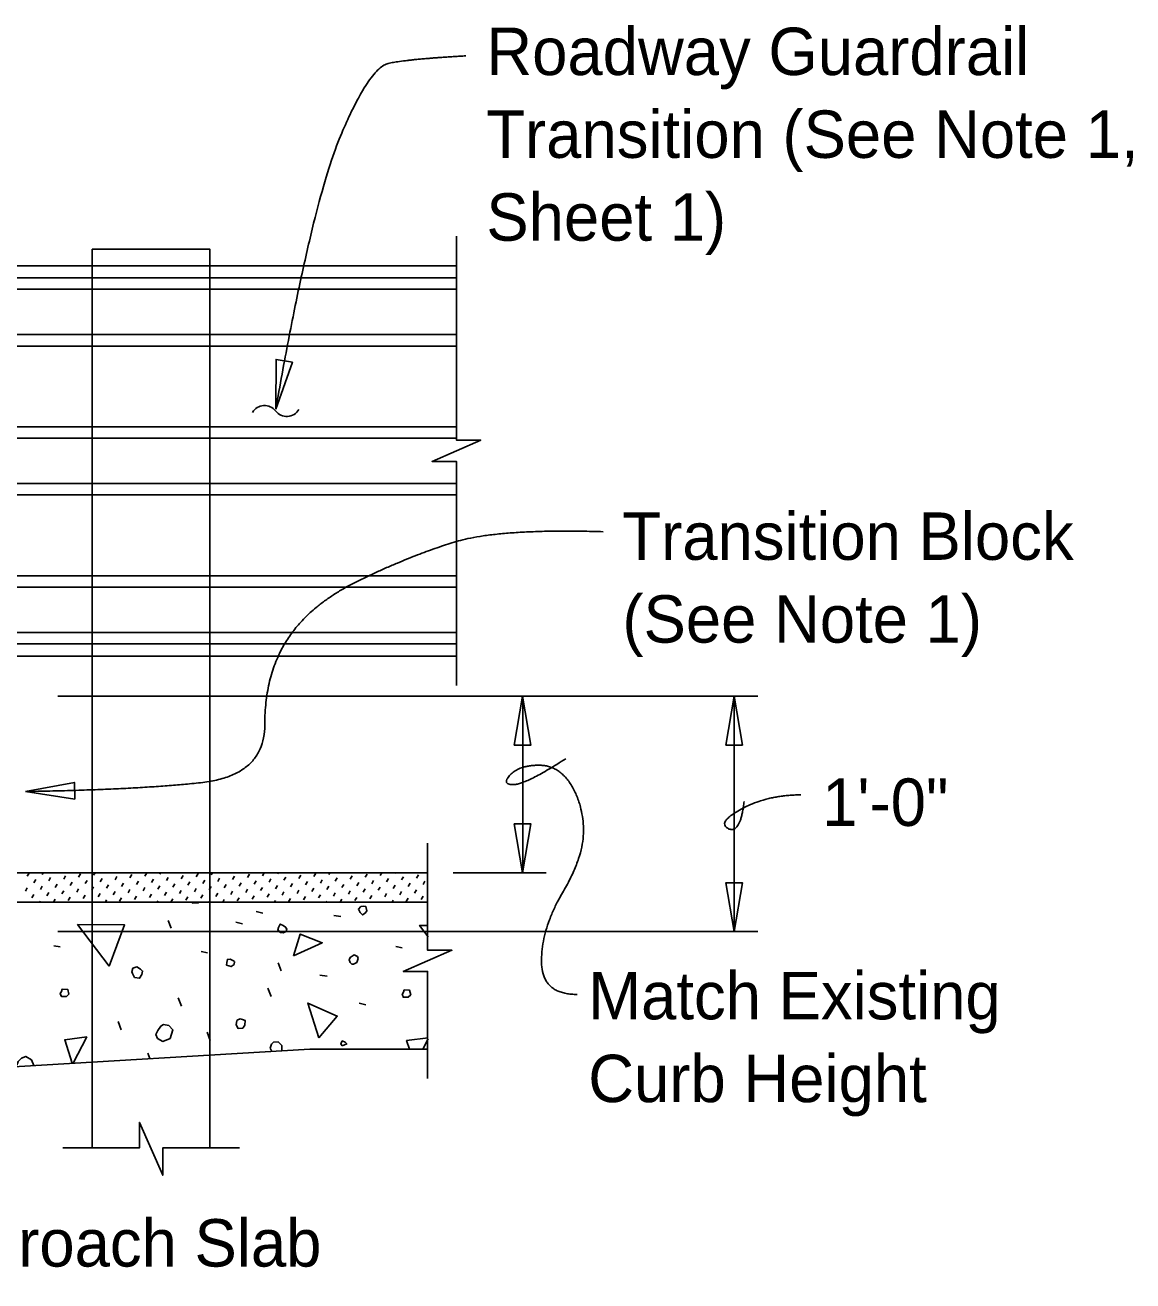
# Model space of a CAD drawing. Extents: x 1 to 39.2, y 0 to 26.
# Drawn here: x 9.7 to 14.41, y 9.08 to 14.42 of the extents above; entities that cross this region are included whole.
import ezdxf

# ---------------------------------------------------------------- set-up
doc = ezdxf.new("R2010")
doc.units = 0
for name, color, linetype in [('Dimension', 7, 'Continuous'), ('Miscellaneous', 7, 'Continuous'), ('TextStructures', 7, 'Continuous'), ('TrafBarrierConc', 7, 'Continuous')]:
    doc.layers.add(name, color=color, linetype=linetype)

# ---------------------------------------------------------------- blocks, each defined once
blk = doc.blocks.new('Terminator-Arrow')
at = {"layer": 'Dimension'}
blk.add_lwpolyline([(0, 0), (-0.00041, 0.000069), (-0.00041, -0.000069)], close=True, dxfattribs=at)

msp = doc.modelspace()

# ---------------------------------------------------------------- linework, layer by layer
at = {"layer": 'Dimension'}
for p, q in [((9.837, 11.5696), (12.8113, 11.5696)), ((11.8124, 11.5697), (11.8124, 10.8196)), ((12.7116, 11.5697), (12.7116, 10.5697)), ((11.5174, 10.8196), (11.9121, 10.8196)), ((9.837, 10.5696), (12.8113, 10.5696))]:
    msp.add_line(p, q, dxfattribs=at)
for points in [[(11.5305, 11.6145), (11.5305, 12.568), (11.4272, 12.568), (11.5305, 12.613), (11.6338, 12.658), (11.5305, 12.658), (11.5305, 13.5246)], [(11.408, 9.9446), (11.408, 10.3996), (11.3047, 10.3996), (11.408, 10.4446), (11.5113, 10.4896), (11.408, 10.4896), (11.408, 10.9446)], [(10.608, 9.6494), (10.2827, 9.6494), (10.2827, 9.5332), (10.1833, 9.7582), (10.1833, 9.6494), (9.858, 9.6494)]]:
    msp.add_lwpolyline(points, dxfattribs=at)
for points in [[(10.7624, 12.7902), (10.8335, 12.989), (10.7641, 13.0014)], [(9.6994, 11.1645), (9.9082, 11.1327), (9.907, 11.2033)]]:
    msp.add_lwpolyline(points, close=True, dxfattribs=at)
for centre, start, end in [((10.7151, 12.7456), 37.7255, 149.4528), ((10.8094, 12.8185), 217.7255, 329.4528)]:
    msp.add_arc(centre, 0.0596, start, end, dxfattribs=at)
for points in [[(11.5699, 14.2915), (11.3198, 14.2772), (11.1626, 14.2414), (10.9196, 13.6766), (10.7624, 12.7901)], [(12.1548, 12.2689), (11.7093, 12.2826), (11.3323, 12.166), (10.9117, 11.9627), (10.7162, 11.6653), (10.7162, 11.2315), (10.1686, 11.1723), (9.6993, 11.1645)], [(12.0432, 10.3021), (11.8924, 10.3021), (11.8924, 10.5833), (12.0706, 10.8852), (12.0706, 11.1047), (11.9678, 11.2762), (11.7965, 11.2762), (11.7211, 11.1939), (11.8239, 11.1939), (11.9952, 11.3036)], [(12.7531, 11.1222), (12.7371, 10.9808), (12.6357, 11.0328), (12.8531, 11.1502), (12.9944, 11.1502)]]:
    msp.add_open_spline(points, degree=2, dxfattribs=at)
at = {"layer": 'Miscellaneous'}
for p, q in [((5.6871, 13.3996), (11.533, 13.3996)), ((5.6871, 13.3475), (11.533, 13.3475)), ((5.6871, 13.2992), (11.533, 13.2992)), ((5.6871, 13.1064), (11.533, 13.1064)), ((5.6871, 13.0582), (11.533, 13.0582)), ((5.6871, 12.7142), (11.533, 12.7142)), ((5.6871, 12.666), (11.533, 12.666)), ((5.6871, 12.4732), (11.533, 12.4732)), ((5.6871, 12.4251), (11.533, 12.4251)), ((5.6871, 12.0811), (11.533, 12.0811)), ((5.6871, 12.0329), (11.533, 12.0329)), ((5.6871, 11.8401), (11.533, 11.8401)), ((5.6871, 11.7918), (11.533, 11.7918)), ((5.6871, 11.7395), (11.533, 11.7395)), ((9.7068, 10.8041), (9.7149, 10.8181)), ((9.7345, 10.7764), (9.7426, 10.7904)), ((9.7703, 10.8122), (9.7747, 10.8196)), ((9.798, 10.7845), (9.8061, 10.7985)), ((9.8615, 10.7926), (9.8696, 10.8066)), ((9.925, 10.8007), (9.9331, 10.8147)), ((9.9527, 10.773), (9.9608, 10.787)), ((9.9885, 10.8088), (9.9948, 10.8196)), ((10.0162, 10.7811), (10.0243, 10.7951)), ((10.052, 10.8169), (10.0536, 10.8196)), ((10.0797, 10.7892), (10.0878, 10.8032)), ((10.1432, 10.7973), (10.1513, 10.8113)), ((10.1709, 10.7696), (10.179, 10.7836)), ((10.2067, 10.8054), (10.2148, 10.8194)), ((10.2344, 10.7777), (10.2425, 10.7917)), ((10.2702, 10.8135), (10.2737, 10.8196)), ((10.2979, 10.7858), (10.306, 10.7998)), ((10.3614, 10.7939), (10.3695, 10.8079)), ((10.4249, 10.802), (10.433, 10.816)), ((10.4525, 10.7743), (10.4607, 10.7883)), ((10.4883, 10.8101), (10.4939, 10.8196)), ((10.516, 10.7824), (10.5241, 10.7964)), ((10.5518, 10.8182), (10.5527, 10.8196)), ((10.5795, 10.7905), (10.5876, 10.8045)), ((10.643, 10.7986), (10.6511, 10.8126)), ((10.6707, 10.7709), (10.6788, 10.7849)), ((10.7065, 10.8067), (10.714, 10.8196)), ((10.7342, 10.779), (10.7423, 10.793)), ((10.77, 10.8148), (10.7728, 10.8196)), ((10.7977, 10.7871), (10.8058, 10.8011)), ((10.8612, 10.7952), (10.8693, 10.8092)), ((10.9247, 10.8033), (10.9328, 10.8173)), ((10.9524, 10.7756), (10.9605, 10.7896)), ((10.9882, 10.8114), (10.9929, 10.8196)), ((11.0159, 10.7837), (11.024, 10.7977)), ((11.0517, 10.8195), (11.0517, 10.8196)), ((11.0794, 10.7918), (11.0875, 10.8058)), ((11.1429, 10.7999), (11.151, 10.8139)), ((11.1706, 10.7722), (11.1787, 10.7862)), ((11.2064, 10.808), (11.2131, 10.8196)), ((11.234, 10.7804), (11.2422, 10.7943)), ((11.2698, 10.8161), (11.2719, 10.8196)), ((11.2975, 10.7885), (11.3056, 10.8024)), ((11.361, 10.7966), (11.3691, 10.8106)), ((11.3887, 10.7689), (11.3968, 10.7829)), ((9.6987, 10.7406), (9.7068, 10.7546)), ((9.7622, 10.7487), (9.7703, 10.7627)), ((9.7899, 10.721), (9.798, 10.735)), ((9.8257, 10.7568), (9.8338, 10.7708)), ((9.8534, 10.7291), (9.8615, 10.7431)), ((9.8892, 10.7649), (9.8973, 10.7789)), ((9.9169, 10.7372), (9.925, 10.7512)), ((9.9804, 10.7453), (9.9885, 10.7593)), ((10.0081, 10.7176), (10.0162, 10.7316)), ((10.0439, 10.7534), (10.052, 10.7674)), ((10.0716, 10.7257), (10.0797, 10.7397)), ((10.1074, 10.7615), (10.1155, 10.7755)), ((10.1351, 10.7338), (10.1432, 10.7478)), ((10.1986, 10.7419), (10.2067, 10.7559)), ((10.2621, 10.75), (10.2702, 10.764)), ((10.2898, 10.7223), (10.2979, 10.7363)), ((10.3256, 10.7581), (10.3337, 10.7721)), ((10.3533, 10.7304), (10.3614, 10.7444)), ((10.3891, 10.7662), (10.3972, 10.7802)), ((10.4168, 10.7385), (10.4249, 10.7525)), ((10.4802, 10.7466), (10.4883, 10.7606)), ((10.5079, 10.7189), (10.516, 10.7329)), ((10.5437, 10.7547), (10.5518, 10.7687)), ((10.5714, 10.727), (10.5795, 10.741)), ((10.6072, 10.7628), (10.6153, 10.7768)), ((10.6349, 10.7351), (10.643, 10.7491)), ((10.6984, 10.7432), (10.7065, 10.7572)), ((10.7261, 10.7155), (10.7342, 10.7295)), ((10.7619, 10.7513), (10.77, 10.7653)), ((10.7896, 10.7236), (10.7977, 10.7376)), ((10.8254, 10.7594), (10.8335, 10.7734)), ((10.8531, 10.7317), (10.8612, 10.7457)), ((10.8889, 10.7675), (10.897, 10.7815)), ((10.9166, 10.7398), (10.9247, 10.7538)), ((10.9801, 10.7479), (10.9882, 10.7619)), ((11.0078, 10.7202), (11.0159, 10.7342)), ((11.0436, 10.756), (11.0517, 10.77)), ((11.0713, 10.7284), (11.0794, 10.7423)), ((11.1071, 10.7641), (11.1152, 10.7781)), ((11.1348, 10.7365), (11.1429, 10.7504)), ((11.1983, 10.7446), (11.2064, 10.7585)), ((11.2259, 10.7169), (11.234, 10.7309)), ((11.2617, 10.7527), (11.2698, 10.7667)), ((11.2894, 10.725), (11.2975, 10.739)), ((11.3252, 10.7608), (11.3333, 10.7748)), ((11.3529, 10.7331), (11.361, 10.7471)), ((9.7264, 10.7129), (9.7345, 10.7269)), ((9.7596, 10.6946), (9.7622, 10.6992)), ((9.8184, 10.6946), (9.8257, 10.7073)), ((9.8811, 10.7014), (9.8892, 10.7154)), ((9.9446, 10.7095), (9.9527, 10.7235)), ((9.9797, 10.6946), (9.9804, 10.6958)), ((10.0385, 10.6946), (10.0439, 10.7039)), ((10.0993, 10.698), (10.1074, 10.712)), ((10.1628, 10.7061), (10.1709, 10.7201)), ((10.2263, 10.7142), (10.2344, 10.7282)), ((10.2587, 10.6946), (10.2621, 10.7005)), ((10.3175, 10.6946), (10.3256, 10.7086)), ((10.381, 10.7027), (10.3891, 10.7167)), ((10.4444, 10.7108), (10.4525, 10.7248)), ((10.4788, 10.6946), (10.4802, 10.6971)), ((10.5376, 10.6946), (10.5437, 10.7052)), ((10.5991, 10.6993), (10.6072, 10.7133)), ((10.6626, 10.7074), (10.6707, 10.7214)), ((10.7577, 10.6946), (10.7619, 10.7018)), ((10.8173, 10.6959), (10.8254, 10.7099)), ((10.8808, 10.704), (10.8889, 10.718)), ((10.9443, 10.7121), (10.9524, 10.7261)), ((10.9779, 10.6946), (10.9801, 10.6984)), ((11.0367, 10.6946), (11.0436, 10.7065)), ((11.099, 10.7007), (11.1071, 10.7146)), ((11.1625, 10.7088), (11.1706, 10.7228)), ((11.198, 10.6946), (11.1983, 10.6951)), ((11.2568, 10.6946), (11.2617, 10.7032)), ((11.3171, 10.6973), (11.3252, 10.7113)), ((11.3806, 10.7054), (11.3887, 10.7194)), ((10.6792, 10.6539), (10.7075, 10.6469)), ((11.0098, 10.638), (11.0398, 10.6327)), ((10.3186, 10.5832), (10.3062, 10.6168)), ((10.5926, 10.6097), (10.6209, 10.6027)), ((9.8201, 10.509), (9.8466, 10.5037)), ((10.4459, 10.4842), (10.4724, 10.4789)), ((11.2732, 10.5054), (11.2997, 10.5001)), ((10.7853, 10.4029), (10.7729, 10.4365)), ((10.9497, 10.3835), (10.9815, 10.3799)), ((10.7428, 10.2933), (10.7287, 10.3287)), ((10.3628, 10.2527), (10.3486, 10.288)), ((11.1176, 10.265), (11.1459, 10.258)), ((10.1064, 10.1519), (10.0923, 10.1872)), ((10.4847, 10.1059), (10.4706, 10.1413)), ((10.2282, 10.0294), (10.2196, 10.0529))]:
    msp.add_line(p, q, dxfattribs=at)
for points in [[(9.9829, 9.6494), (9.9829, 13.4695), (10.4829, 13.4695), (10.4829, 9.6494)], [(10.4072, 10.6946), (10.4105, 10.6893), (10.4335, 10.6911), (10.4371, 10.6946)], [(11.1211, 10.6504), (11.1317, 10.6398), (11.1424, 10.6469), (11.1494, 10.6575), (11.1459, 10.6752), (11.1371, 10.6769), (11.1247, 10.6752), (11.1141, 10.6645), (11.1211, 10.6504)], [(10.0552, 10.4224), (9.9208, 10.5991), (10.1206, 10.5974), (10.0552, 10.4224)], [(10.7817, 10.5656), (10.7941, 10.5638), (10.8065, 10.5691), (10.81, 10.5797), (10.8047, 10.5885), (10.7941, 10.5956), (10.7817, 10.6009), (10.7747, 10.5868), (10.7711, 10.5762), (10.7817, 10.5656)], [(11.4105, 10.5475), (11.3739, 10.5956), (11.4105, 10.5953)], [(10.8383, 10.4666), (10.8666, 10.5585), (10.9603, 10.5214), (10.8383, 10.4666)], [(11.0858, 10.4312), (11.0929, 10.4312), (11.107, 10.4383), (11.1123, 10.4542), (11.1105, 10.463), (11.0964, 10.4701), (11.0787, 10.4595), (11.0752, 10.4489), (11.0787, 10.4383), (11.0858, 10.4312)], [(10.1542, 10.3905), (10.163, 10.3746), (10.1842, 10.3711), (10.1931, 10.387), (10.1966, 10.4011), (10.1878, 10.41), (10.1719, 10.4188), (10.1559, 10.4135), (10.1506, 10.3976), (10.1542, 10.3905)], [(10.5537, 10.4259), (10.5731, 10.4206), (10.5855, 10.4294), (10.5873, 10.4418), (10.5837, 10.4453), (10.5696, 10.4524), (10.5572, 10.4506), (10.5555, 10.4383), (10.5537, 10.4259)], [(9.8519, 10.2933), (9.8731, 10.2933), (9.8837, 10.3039), (9.8784, 10.3234), (9.8554, 10.3251), (9.8519, 10.3145), (9.8466, 10.3057), (9.8519, 10.2933), (9.8483, 10.2969)], [(11.305, 10.2898), (11.3262, 10.2898), (11.3368, 10.3004), (11.3315, 10.3198), (11.3085, 10.3216), (11.305, 10.311), (11.2997, 10.3022), (11.305, 10.2898), (11.3015, 10.2933)], [(10.9461, 10.1183), (10.8984, 10.265), (11.0239, 10.2102), (10.9461, 10.1183)], [(10.5943, 10.1731), (10.6032, 10.1572), (10.6226, 10.159), (10.6315, 10.1713), (10.6332, 10.1908), (10.6209, 10.1961), (10.612, 10.1979), (10.6014, 10.1943), (10.5979, 10.1908), (10.5943, 10.1731)], [(10.2602, 10.1148), (10.2832, 10.1024), (10.3133, 10.1148), (10.3256, 10.1519), (10.308, 10.1696), (10.285, 10.1749), (10.2744, 10.1678), (10.262, 10.1484), (10.2532, 10.1324), (10.2602, 10.1148)], [(9.8981, 10.0098), (9.866, 10.1095), (9.9597, 10.1218), (9.9021, 10.0101)], [(10.7882, 10.0626), (10.7888, 10.0635), (10.7888, 10.0847), (10.7729, 10.1006), (10.7534, 10.0989), (10.7446, 10.09), (10.7393, 10.0741)], [(11.0451, 10.083), (11.0646, 10.0918), (11.0575, 10.0989), (11.0451, 10.1042), (11.0398, 10.0918), (11.0451, 10.083)], [(11.3308, 10.0696), (11.3191, 10.1059), (11.4105, 10.118)], [(11.4105, 10.1138), (11.3877, 10.0696)], [(9.7347, 10.0001), (9.7246, 10.0246), (9.6999, 10.0388), (9.6822, 10.0317), (9.668, 10.0175), (9.6627, 10.0016)], [(10.7393, 10.0741), (10.7463, 10.0601)]]:
    msp.add_lwpolyline(points, dxfattribs=at)
at = {"layer": 'TrafBarrierConc'}
for p, q in [((5.687, 10.8196), (11.4105, 10.8196)), ((7.6871, 10.6946), (11.4105, 10.6946)), ((6.687, 9.8196), (10.907, 10.0696)), ((10.907, 10.0696), (11.4105, 10.0696))]:
    msp.add_line(p, q, dxfattribs=at)

# ---------------------------------------------------------------- block references
at = {"layer": 'Dimension', "xscale": 506.349, "yscale": -512.1577380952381}
for p, rotation in [((11.8118, 11.5694), 90), ((12.711, 11.5694), 90), ((11.812, 10.8193), -90), ((12.711, 10.5693), -90)]:
    msp.add_blockref('Terminator-Arrow', p, dxfattribs=dict(at, rotation=rotation))

# ---------------------------------------------------------------- texts
at = {"layer": 'Dimension'}
for s, p in [('Roadway Guardrail ', (11.6577, 14.2098)), ('Transition (See Note 1,', (11.6577, 13.8578)), ('Sheet 1)', (11.6577, 13.5058)), ('Transition Block', (12.236, 12.1493)), ('(See Note 1)', (12.236, 11.7973)), ('Match Existing ', (12.0908, 10.1962)), ('Curb Height', (12.0908, 9.8442))]:
    msp.add_text(s, height=0.2016, dxfattribs=at).set_placement(p)
at = {"layer": 'TextStructures'}
for s, p in [('1\'-0"', (13.085, 11.0184)), ('Existing Approach Slab', (8.1696, 9.1453))]:
    msp.add_text(s, height=0.2016, dxfattribs=at).set_placement(p)

doc.saveas('drawing.dxf')
